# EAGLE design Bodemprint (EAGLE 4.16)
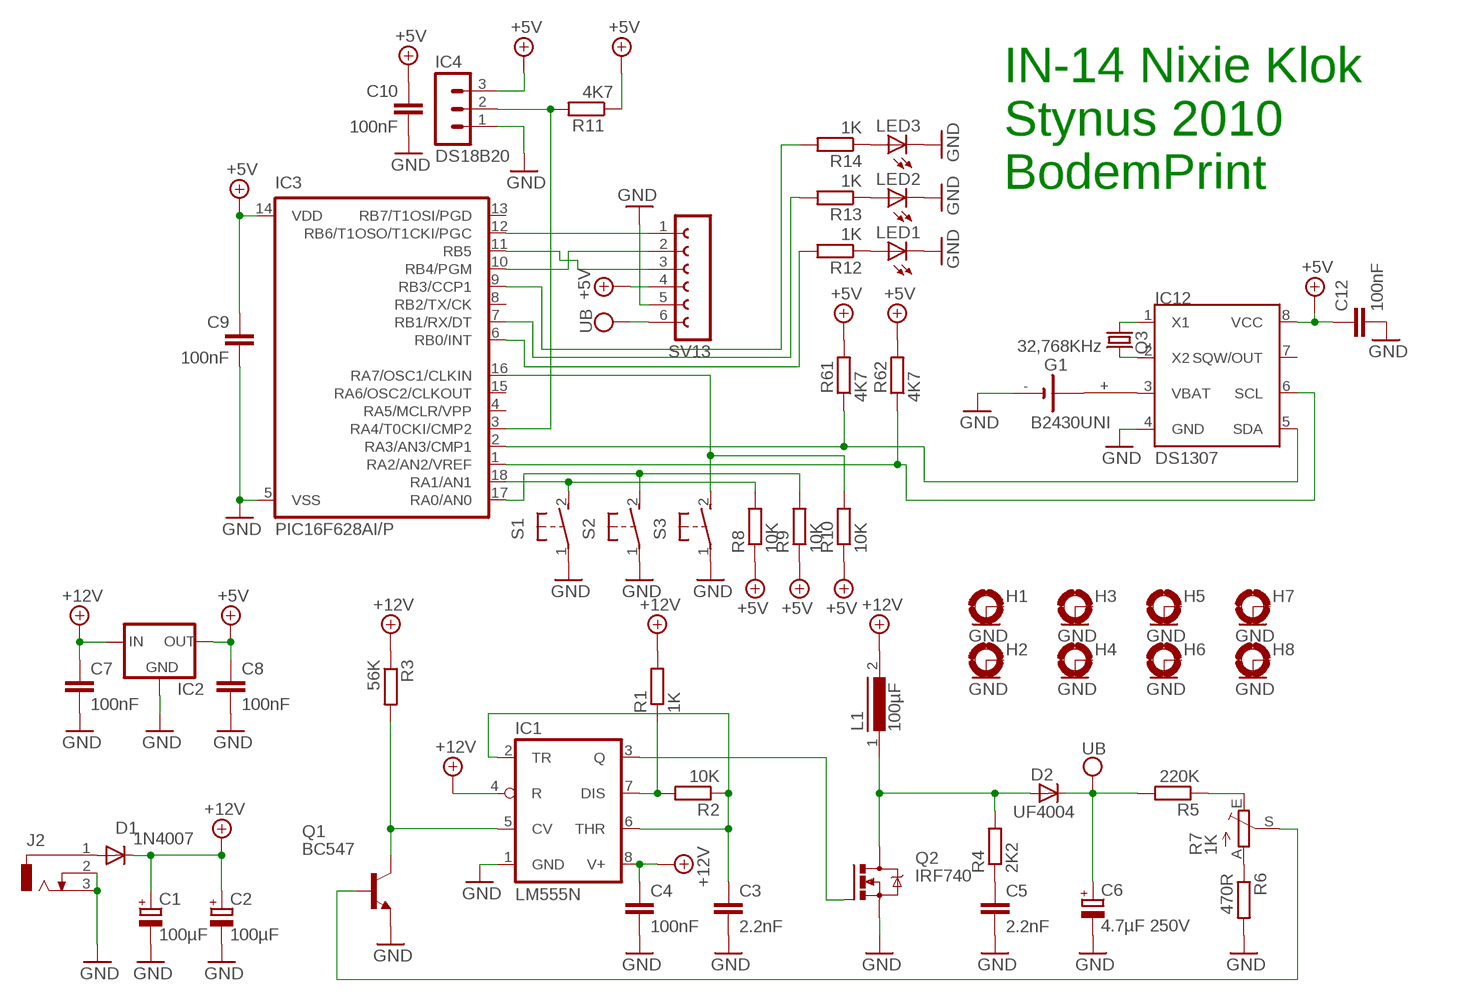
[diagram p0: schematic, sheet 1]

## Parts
C1  100µF  CPOL-EUE3.5-8  [E3,5-8]
C2  100µF  CPOL-EUE3.5-8  [E3,5-8]
C3  2.2nF  C-EU050-025X075  [C050-025X075]
C4  100nF  C-EUC0805  [C0805]
C5  2.2nF  C-EU025-024X044  [C025-024X044]
C6  4.7µF 250V  CPOL-EUE3.5-8  [E3,5-8]
C7  100nF  C-EUC0805  [C0805]
C8  100nF  C-EUC0805  [C0805]
C9  100nF  C-EUC0805  [C0805]
C10  100nF  C-EUC0805  [C0805]
C12  100nF  C-EU050-025X075  [C050-025X075]
D1  1N4007  1N4004  [DO41-10]
D2  UF4004  1N4004  [DO41-10]
G1  B2430UNI  [B2430UNI]
H1  MOUNT-PAD-ROUND3.0  [3,0-PAD]
H2  MOUNT-PAD-ROUND3.0  [3,0-PAD]
H3  MOUNT-PAD-ROUND3.0  [3,0-PAD]
H4  MOUNT-PAD-ROUND3.0  [3,0-PAD]
H5  MOUNT-PAD-ROUND3.0  [3,0-PAD]
H6  MOUNT-PAD-ROUND3.0  [3,0-PAD]
H7  MOUNT-PAD-ROUND3.0  [3,0-PAD]
H8  MOUNT-PAD-ROUND3.0  [3,0-PAD]
IC1  LM555N  [DIL08]
IC2  78XXL  [78XXL]
IC3  PIC16F628AI/P  [DIL18]
IC4  DS18B20  MA03-1  [MA03-1]
IC12  DS1307  [DIL8]
J2  DCJ0202  [DCJ0202]
L1  100µF  82114R  [82114R]
LED1  LED3MM  [LED3MM]
LED2  LED3MM  [LED3MM]
LED3  LED3MM  [LED3MM]
Q1  BC547  [TO92]
Q2  IRF740  [TO220BV]
Q3  32,768KHz  CRYSTALTC38H  [TC38H]
R1  1K  R-EU_R0805  [R0805]
R2  10K  R-EU_R0805  [R0805]
R3  56K  R-EU_R0805  [R0805]
R4  2K2  R-EU_0207/7  [0207/7]
R5  220K  R-EU_0207/7  [0207/7]
R6  470R  R-EU_0207/7  [0207/7]
R7  1K  TRIM_EU-S63P  [S63P]
R8  10K  R-EU_R0805  [R0805]
R9  10K  R-EU_R0805  [R0805]
R10  10K  R-EU_R0805  [R0805]
R11  4K7  R-EU_0204/7  [0204/7]
R12  1K  R-EU_R0805  [R0805]
R13  1K  R-EU_R0805  [R0805]
R14  1K  R-EU_R0805  [R0805]
R61  4K7  R-EU_0204/7  [0204/7]
R62  4K7  R-EU_0204/7  [0204/7]
S1  31-XX  [B3F-31XX]
S2  31-XX  [B3F-31XX]
S3  31-XX  [B3F-31XX]
SV13  FE06-1  [FE06]

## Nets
+5V: C8.1 C9.1 C10.1 C12.1 IC2.OUT IC3.14(VDD) IC4.3 IC12.8(VCC) R8.1 R9.1 R10.1 R11.1 R61.2 R62.2 SV13.4
+12V: C1.+ C2.+ C4.1 C7.1 D1.C IC1.4(R) IC1.8(V+) IC2.IN L1.2 R1.2 R3.1
GND: C1.- C2.- C3.2 C4.2 C5.2 C6.- C7.2 C8.2 C9.2 C10.2 C12.2 G1.- H1.B3,0(MOUNT) H2.B3,0(MOUNT) H3.B3,0(MOUNT) H4.B3,0(MOUNT) H5.B3,0(MOUNT) H6.B3,0(MOUNT) H7.B3,0(MOUNT) H8.B3,0(MOUNT) IC1.1(GND) IC2.GND IC3.5(VSS) IC4.1 IC12.4(GND) J2.2 J2.3 LED1.K(C) LED2.K(C) LED3.K(C) Q1.1(E) Q2.S R6.2 S1.1(P) S2.1(P) S3.1(P) SV13.5
N$1: IC1.7(DIS) R1.1 R2.2
N$2: C3.1 IC1.2(TR) IC1.6(THR) R2.1
N$3: IC1.5(CV) Q1.3(C) R3.2
N$4: D2.A L1.1 Q2.D R4.2
N$5: IC1.3(Q) Q2.G
N$6: C5.1 R4.1
N$7: Q1.2(B) R7.S
N$8: IC12.1(X1) Q3.1
N$9: D1.A J2.1
N$10: R5.1 R7.E
N$11: R6.1 R7.A
N$12: IC12.2(X2) Q3.2
N$13: IC3.11(RB5) SV13.3
N$14: IC3.10(RB4/PGM) SV13.2
N$15: IC3.18(RA1/AN1) R8.2 S1.2(S)
N$16: IC3.17(RA0/AN0) R9.2 S2.2(S)
N$17: IC3.16(RA7/OSC1/CLKIN) R10.2 S3.2(S)
N$18: IC3.3(RA4/T0CKI/CMP2) IC4.2 R11.2
N$19: LED1.A R12.1
N$20: LED2.A R13.1
N$21: LED3.A R14.1
N$22: IC3.6(RB0/INT) R12.2
N$23: IC3.7(RB1/RX/DT) R13.2
N$24: IC3.9(RB3/CCP1) R14.2
N$108: IC3.12(RB6/T1OSO/T1CKI/PGC) SV13.1
N$153: G1.+ IC12.3(VBAT)
N$154: IC3.2(RA3/AN3/CMP1) IC12.5(SDA) R61.1
N$155: IC3.1(RA2/AN2/VREF) IC12.6(SCL) R62.1
VSS: C6.+ D2.C R5.2 SV13.6 ; supply symbol labelled UB
Unconnected: G1.+@1(+) G1.+@2(+) G1.+@3(+) G1.+@4(+) G1.-@1(-) IC3.4(RA5/MCLR/VPP) IC3.8(RB2/TX/CK) IC3.13(RB7/T1OSI/PGD) IC3.15(RA6/OSC2/CLKOUT) IC12.7(SQW/OUT)

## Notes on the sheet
- IN-14 Nixie Klok
- Stynus 2010
- BodemPrint

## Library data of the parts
C1 C2 C6 = rcl:CPOL-EU: POLARIZED CAPACITOR, European symbol
C3-C5 C7-C10 C12 = rcl:C-EU: CAPACITOR, European symbol
D1 D2 = diode:1N4004: DIODE
G1 = battery:B2430UNI: LI BATTERY
H1-H8 = holes:MOUNT-PAD-ROUND: MOUNTING PAD, round
IC1 = linear:*555: TIMER
IC2 = v-reg:78XXL: VOLTAGE REGULATOR
IC3 = microchip-4:PIC16F628*: MICROCONTROLLER PIC16F628(A) 16 I/O One 16-bit timer (TMR0) Two 8-bit timer (TMR0) Two comparators USART CCP/PWM Precision 4 MHz internal oscillator 2k Program Flash memory 224 bytes SRAM 128 bytes EEPROM
IC4 = con-lstb:MA03-1: PIN HEADER
IC12 = dallas-1:DS1307: I2C Serial RTC w/56 bytes battery backed RAM
J2 = con-jack__:DCJ0202: DC POWER JACK Source: DCJ0202.pdf
L1 = inductors:82114R: INDUCTOR
LED1-LED3 = led:LED: LED
Q1 = transistor-npn:BC547*: NPN Transistor
Q2 = transistor-power:IRF740: N-CHANNEL MOS FET
Q3 = crystal:CRYSTAL: CRYSTAL
R1-R6 R8-R14 R61 R62 = rcl:R-EU_: RESISTOR, European symbol
R7 = pot:TRIM_EU-: POTENTIOMETER
S1-S3 = switch-omron:31-XX: OMRON SWITCH
SV13 = con-lsta:FE06-1: FEMALE HEADER

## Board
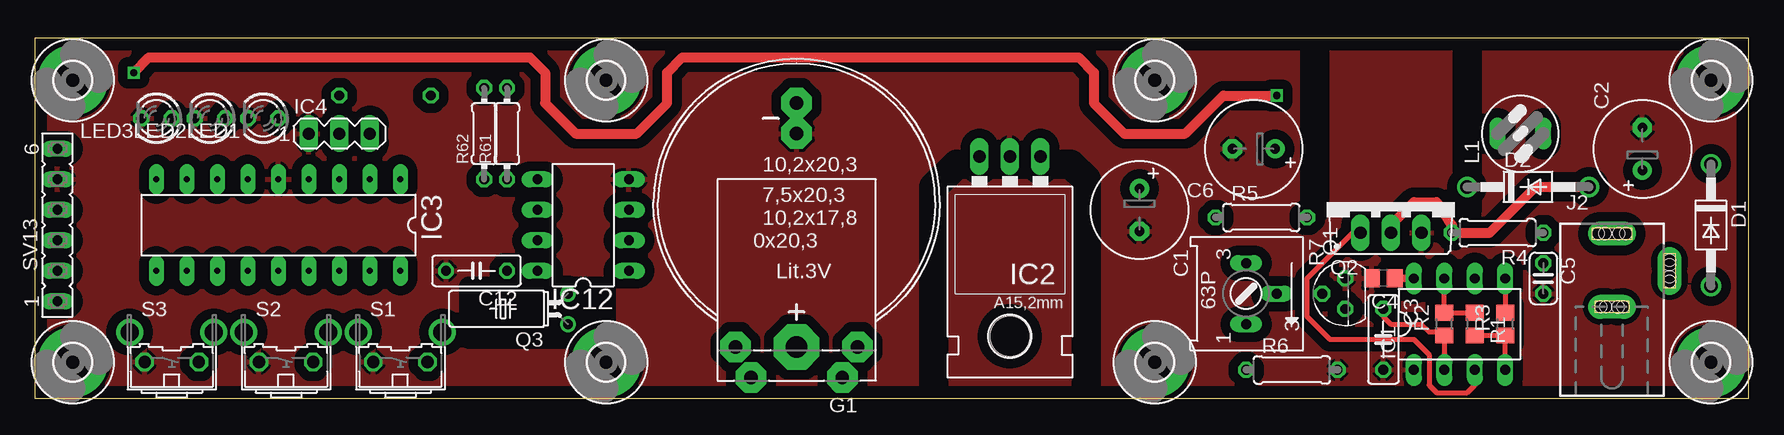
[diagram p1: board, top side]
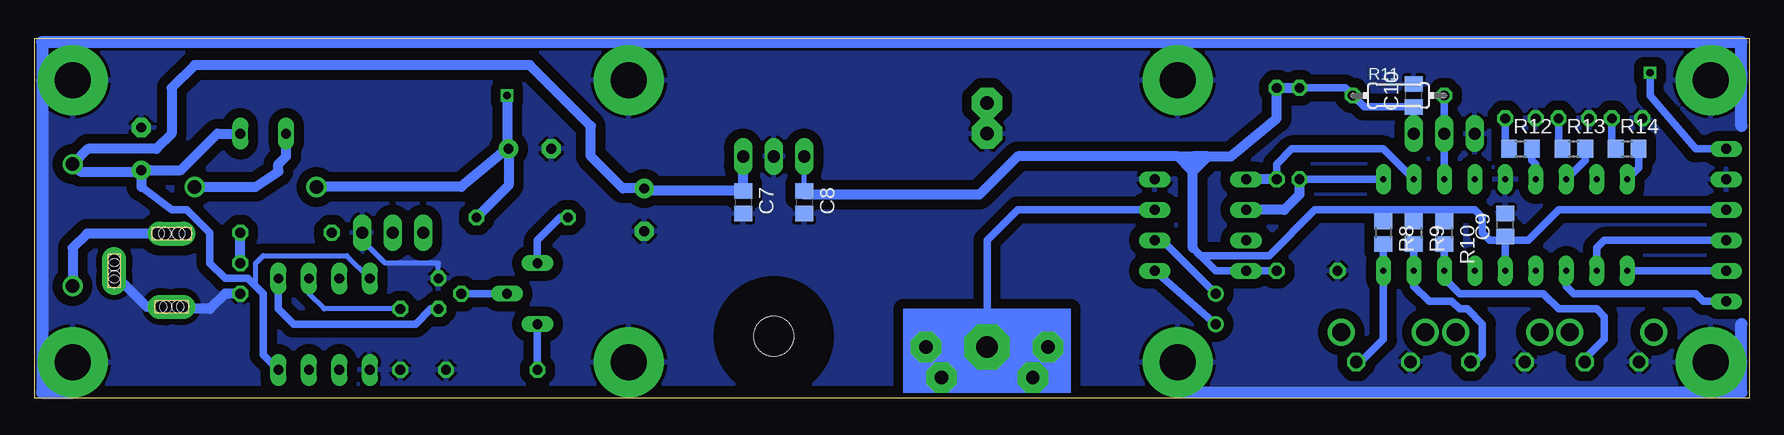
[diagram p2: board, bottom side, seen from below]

Size 142.85 x 30 mm. Coordinates in mm from the lower left corner, seen from the top.
Outline: 0,0 142.85,0 142.85,30 0,30 0,0
Copper layers (1*16): Top 0.035mm / dielectric 1.5mm / Bottom 0.035mm
Design rules "default": minimum track width 10mil, minimum drill 24mil, track to track 8mil, track to pad 8mil, pad to pad 8mil, via to via 8mil, smd to smd 8mil, copper to edge 40mil, drill to drill 8mil, minimum pad ring 10mil, minimum via ring 8mil, stop-mask expansion 4mil, vias tented up to drill 0mil, thermal gap 10mil
tRestrict: area 36.2,4.9 to 47.6,9.4; 7 lines

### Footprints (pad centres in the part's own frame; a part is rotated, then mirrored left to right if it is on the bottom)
E3,5-8 = drill 0.813 pad 1.6 round: + -1.778,0 | drill 0.813 pad 1.6 octagon: - 1.778,0
C050-025X075 = drill 0.813 octagon: 1 -2.54,0; 2 2.54,0
C0805 = smd 1.3 x 1.5: 1 -0.95,0; 2 0.95,0
C025-024X044 = drill 0.813 octagon: 1 -1.27,0; 2 1.27,0
DO41-10 = drill 1.118 round: A 5.08,0; C -5.08,0
B2430UNI = drill 1.118 pad 2.54 octagon: + 3.81,14.605; +@1 -3.81,14.605; +@2 -5.08,12.065; +@3 5.08,12.065; - 0,-5.715; -@1 0,-8.255 | drill 1.803 pad 3.81 octagon: +@4 0,12.065
3,0-PAD = drill 3 pad 5.842 round: B3,0 0,0
DIL08 = drill 0.813 long: 1 -3.81,-3.81; 2 -1.27,-3.81; 3 1.27,-3.81; 4 3.81,-3.81; 5 3.81,3.81; 6 1.27,3.81; 7 -1.27,3.81; 8 -3.81,3.81
78XXL = drill 1.016 long: GND 0,-3.81; IN -2.54,-3.81; OUT 2.54,-3.81 | hole 3.302: 0,11.176
DIL18 = drill 0.5 pad 1.27 long: 1 -10.16,-3.81; 2 -7.62,-3.81; 3 -5.08,-3.81; 4 -2.54,-3.81; 5 0,-3.81; 6 2.54,-3.81; 7 5.08,-3.81; 8 7.62,-3.81; 9 10.16,-3.81; 10 10.16,3.81; 11 7.62,3.81; 12 5.08,3.81; 13 2.54,3.81; 14 0,3.81; 15 -2.54,3.81; 16 -5.08,3.81; 17 -7.62,3.81; 18 -10.16,3.81
MA03-1 = drill 1.016 long: 1 -2.54,0; 2 0,0; 3 2.54,0
DIL8 = drill 0.813 long: 1 -3.81,-3.81; 2 -1.27,-3.81; 3 1.27,-3.81; 4 3.81,-3.81; 5 3.81,3.81; 6 1.27,3.81; 7 -1.27,3.81; 8 -3.81,3.81
DCJ0202 = drill 1 pad 2 long: 1 0,3.1; 2 4.8,0; 3 0,-3 | hole 1: -1.143,3.111; 1.143,3.111; 0.572,3.111; -0.572,3.111; 4.794,0.889; 4.794,-0.889; 4.794,-0.508; 4.794,0.508; 0.921,-2.985; -0.921,-2.985; -0.508,-2.985; 0.508,-3.016
82114R = drill 0.813 long: 1 0,1.905; 2 0,-1.905
LED3MM = drill 0.813 octagon: A -1.27,0; K 1.27,0
TO92 = drill 0.813 octagon: 1 1.27,0; 2 0,1.905; 3 -1.27,0
TO220BV = drill 1.016 long: D 0,-2.54; G -2.54,-2.54; S 2.54,-2.54
TC38H = drill 0.813 round: 1 -1.27,0; 2 1.27,0
R0805 = smd 1.3 x 1.5: 1 -0.95,0; 2 0.95,0
0207/7 = drill 0.813 octagon: 1 -3.81,0; 2 3.81,0
S63P = drill 0.813 long: A 2.54,0; E -2.54,0; S 0,2.54
0204/7 = drill 0.813 octagon: 1 -3.81,0; 2 3.81,0
B3F-31XX = drill 1.016 octagon: 1 -2.261,-1.245; 2 2.261,-1.245 | drill 1.499 pad 2.159 round: 3 -3.505,1.245; 4 3.505,1.245
FE06 = drill 0.813 long: 1 -6.35,0; 2 -3.81,0; 3 -1.27,0; 4 1.27,0; 5 3.81,0; 6 6.35,0

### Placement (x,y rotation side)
C1  92.07,15.71 270 top
C2  133.98,20.79 90 top
C3  112.39,4.92 270 top
C4  112.39,10 180 top
C5  125.72,10 270 top
C6  101.59,20.79 180 top
C7  83.81,16.34 270 bottom
C8  78.73,16.34 270 bottom
C9  20.31,14.44 90 bottom
C10  27.93,25.23 90 bottom
C12  36.83,10.63 180 top
D1  139.69,14.44 270 top
D2  124.45,17.61 0 top
G1  63.5,16.34 180 top
H1  3.17,26.5 0 top
H2  3.17,3.01 0 top
H3  47.62,26.5 0 top
H4  47.62,3.01 0 top
H5  93.34,26.5 0 top
H6  93.34,3.01 0 top
H7  139.69,26.5 0 top
H8  139.69,3.01 0 top
IC1  118.74,6.18 0 top
IC2  81.27,16.34 180 top
IC3  20.31,14.44 180 top
IC4  25.39,22.06 0 top
IC12  45.72,14.44 90 top
J2  131.44,10.63 0 top
L1  123.82,22.06 90 top
LED1  19.04,23.33 180 top
LED2  14.6,23.33 180 top
LED3  10.16,23.33 180 top
Q1  109.21,8.73 90 top
Q2  113.02,16.34 0 top
Q3  44.45,7.46 90 top
R1  120.01,6.18 270 top
R2  117.47,6.18 90 top
R3  122.55,6.18 90 top
R4  121.91,13.81 180 top
R5  102.23,15.08 0 top
R6  104.77,2.38 0 top
R7  100.96,8.73 270 top
R8  30.47,13.81 270 bottom
R9  27.93,13.81 270 bottom
R10  25.39,13.81 270 bottom
R11  29.2,25.23 0 bottom
R12  19.04,20.79 0 bottom
R13  14.6,20.79 0 bottom
R14  10.16,20.79 0 bottom
R61  39.37,22.06 90 top
R62  37.46,22.06 90 top
S1  30.47,4.28 0 top
S2  20.95,4.28 0 top
S3  11.43,4.28 0 top
SV13  1.9,14.44 90 top

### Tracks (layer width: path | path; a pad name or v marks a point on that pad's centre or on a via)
+5V
  Bottom 0.406: C8.1 IC2.OUT
  Bottom 0.61: IC12.8 C12.1 44.45,10.63 46.35,12.54 45.72,11.9 40,11.9 36.19,15.71 30.47,15.71 | 20.31,13.17 IC3.14 | 20.31,13.17 21.58,13.17 22.22,13.81 22.22,15.08 22.86,15.71 25.39,15.71 | 25.39,15.71 27.93,15.71 | 27.93,15.71 30.47,15.71 | SV13.4 15.87,15.71 18.41,13.17 20.31,13.17 | 20.31,13.17 C9.1 | 25.39,15.71 R10.1 | 27.93,15.71 R9.1 | 30.47,15.71 R8.1 | R62.2 33.65,25.87 R11.1 32.06,24.29 C10.1 IC4.3
  Bottom 0.813: C8.1 78.73,16.98 64.13,16.98 60.96,20.15 47.62,20.15 | 45.08,20.15 43.18,20.15 39.37,23.33 R61.2 R62.2 | 46.35,12.54 46.35,18.88 | 47.62,20.15 46.35,20.15 | 46.35,18.88 47.62,20.15 | 46.35,18.88 45.08,20.15 | 45.08,20.15 46.35,20.15 | 46.35,20.15 46.35,19.52
+12V
  Top 0.406: R1.2 R3.1 IC1.4
  Top 0.61: IC1.8 C4.1
  Bottom 0.406: IC1.8 116.83,11.9 123.82,11.9 124.45,11.27 124.45,9.36
  Bottom 0.61: 133.98,17.61 131.44,15.71 130.17,15.71 128.27,13.81 128.27,11.27 126.99,10 125.09,10 124.45,9.36 123.82,8.73 123.82,3.64 IC1.4
  Bottom 0.813: 133.98,18.88 C2.+ 133.22,19.01 | 133.98,18.88 139.06,18.88 D1.C 138.42,20.79 132.71,20.79 131.44,22.06 131.44,25.87 129.53,27.77 101.59,27.77 96.52,22.7 96.52,20.15 93.85,17.49 C1.+ 92.07,17.61 91.75,17.29 C7.1 IC2.IN | L1.2 127.63,22.06 130.68,19.01 133.22,19.01 | 133.98,18.88 133.22,19.01 | 133.98,18.88 133.98,17.61
GND
  Bottom 0.406: Q2.S 115.56,13.17 113.66,11.27 109.21,11.27 Q1.1
  Bottom 0.813: J2.2 135.88,10.63 135.88,10 133.52,7.63 J2.3 131.44,7.46 128.27,7.46 126.99,8.73 C5.2
  Bottom 1.016: 3.17,29.68 H1.B3,0 0.63,26.5 0.63,27.14 | 139.69,29.68 142.23,29.68 142.23,26.5 | 47.62,29.68 139.69,29.68 | 3.17,29.68 47.62,29.68 | 142.23,26.5 142.23,0.47 139.69,0.47 H8.B3,0 141.6,3.01 | 3.17,0.47 0.63,0.47 0.63,3.01 | 3.17,0.47 47.62,0.47 H4.B3,0 | 0.63,27.14 0.63,29.68 3.17,29.68 | 47.62,29.68 H3.B3,0 | H5.B3,0 93.34,29.04 | 139.69,29.68 H7.B3,0 | 142.23,26.5 140.33,26.5 | 93.34,0.47 H6.B3,0 | 0.63,3.01 0.63,6.18 | 3.17,0.47 H2.B3,0 0.63,3.01 | 0.63,22.7 0.63,27.14
  pour Bottom (isolate 0.813): -0.01,29.68 142.87,30.31 142.87,0.47 -0.01,-0.17
  pour Top (isolate 0.813): -0.01,29.68 142.87,29.68 142.87,-0.17 -0.01,-0.17
N$1
  Top 0.406: R2.2 R1.1 | R2.2 117.47,6.82 | R2.2 IC1.7
N$2
  Top 0.406: IC1.2 R2.1 117.47,5.55 116.2,5.55 115.56,6.18 114.93,6.18 114.3,6.18 113.02,6.18 112.39,6.82 C3.1
  Bottom 0.406: IC1.6 120.01,8.73 118.74,7.46 C3.1
N$3
  Top 0.406: IC1.5 R3.2
  Bottom 0.61: Q1.3 109.85,7.46 111.12,6.18 121.28,6.18 122.55,7.46 IC1.5
N$4
  Top 0.813: Q2.D 113.02,14.44 114.93,16.34 116.83,16.34 118.1,14.44 R4.2 121.28,13.81 125.09,17.61 D2.A
  Bottom 0.813: D2.A 124.45,17.61 122.55,18.88 122.55,19.52 121.91,20.15 L1.1
N$5
  Top 0.406: Q2.G 109.85,13.81 106.04,10 106.04,6.82 107.94,4.92 114.93,4.92 116.2,3.64 116.2,1.1 116.83,0.47 119.38,0.47 120.01,1.1 IC1.3
N$6
  Bottom 0.813: C5.1 R4.1
N$7
  Bottom 0.61: R7.S Q1.2
N$8
  Bottom 0.61: Q3.1 IC12.1
N$9
  Bottom 0.813: J2.1 138.5,13.73 139.69,12.54 D1.A
N$10
  Bottom 0.61: R7.E 100.96,13.17 99.05,15.08 R5.1
N$11
  Bottom 0.61: R6.1 R7.A
N$12
  Bottom 0.61: Q3.2 48.89,13.17 IC12.2
N$13
  Bottom 0.61: SV13.3 12.06,13.17 12.7,12.54 IC3.11
N$14
  Bottom 0.61: SV13.2 IC3.10
N$15
  Bottom 0.61: S1.2 32.41,3.04 32.38,3.01 30.47,4.92 IC3.18 R8.2
N$16
  Bottom 0.61: S2.2 22.88,3.04 22.86,3.01 22.22,3.64 22.22,6.18 23.49,7.46 24.12,7.46 24.76,8.09 26.66,8.09 27.93,9.36 IC3.17 R9.2
N$17
  Bottom 0.61: S3.2 13.69,3.29 12.06,4.92 12.06,6.82 12.7,7.46 15.87,7.46 17.14,8.73 24.12,8.73 25.39,10 IC3.16 R10.2
N$18
  Bottom 0.61: IC3.3 IC4.2 R11.2
N$19
  Bottom 0.61: R12.1 19.68,20.79 20.31,21.42 LED1.A
N$20
  Bottom 0.61: R13.1 15.24,20.79 15.87,21.42 LED2.A
N$21
  Bottom 0.61: R14.1 10.79,20.79 11.43,21.42 LED3.A
N$22
  Bottom 0.61: R12.2 18.09,19.84 17.77,19.52 IC3.6
N$23
  Bottom 0.61: R13.2 13.65,19.83 IC3.7
N$24
  Bottom 0.61: R14.2 9.21,19.2 IC3.9
N$108
  Bottom 0.61: SV13.1 3.8,8.09 4.44,8.73 14.6,8.73 15.24,9.36 IC3.12
N$153
  Bottom 0.61: G1.+ 60.96,2.38 63.5,6.18 63.5,13.17 60.96,15.71 IC12.3
N$154
  Bottom 0.61: IC3.2 30.47,20.79 38.1,20.79 39.37,19.52 R61.1
  Bottom 0.813: R61.1 IC12.5
N$155
  Bottom 0.61: IC3.1 R62.1
  Bottom 0.813: IC12.6 38.73,15.71 37.46,16.98 R62.1
VSS  (via drill 0.6)
  Top 0.813: v8.25,27.14 9.52,28.41 41.27,28.41 42.54,27.14 42.54,24.6 45.08,22.06 50.16,22.06 52.7,24.6 52.7,27.14 53.97,28.41 86.99,28.41 88.26,27.14 88.26,24.6 90.8,22.06 95.88,22.06 99.05,25.23 v103.5,25.23
  Bottom 0.61: SV13.6 4.44,20.79 8.25,25.23 v8.25,27.14
  Bottom 0.813: D2.C 107.31,17.61 103.5,20.79 | R5.2 103.37,17.74 C6.+ 103.5,20.79 | v103.5,25.23 103.5,20.79
(copper drawn outside any net)
  shapes: Bottom area x1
